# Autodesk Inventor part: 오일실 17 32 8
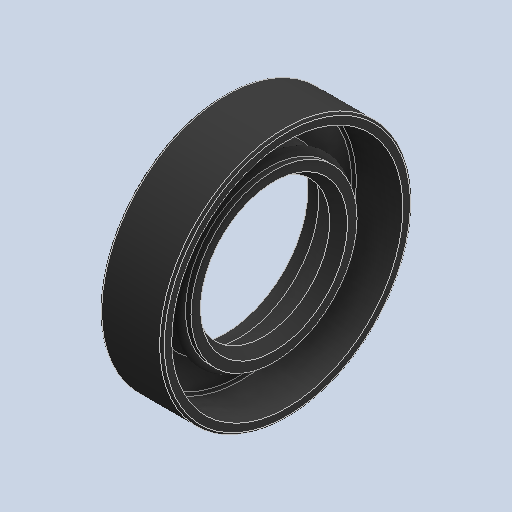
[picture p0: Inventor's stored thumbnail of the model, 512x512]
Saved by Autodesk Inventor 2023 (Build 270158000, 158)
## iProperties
Created: 2024-09
Part Number: 오일실 17 32 8
Material: 고무
Description: 오일-실
Document SubType Name: Modeling
Designer: asung
Density: 0.93 g/cm^3
Appearance: 기본값
Author: jhkim
Sending System: Autodesk Inventor 2025
Preprocessor: ST-DEVELOPER v20
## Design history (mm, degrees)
feature "Solid1"
node "솔리드1"
